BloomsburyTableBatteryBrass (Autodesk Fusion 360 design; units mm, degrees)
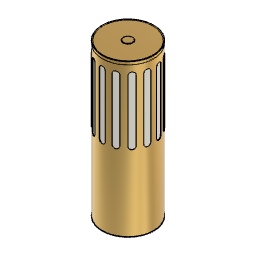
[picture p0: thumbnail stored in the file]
sketch "Sketch2" plane through (0, 0, 0) normal (0, 0, 1) x axis (1, 0, 0)
  circle C1 centre (0, 0) radius 27
  point P1 (0, 0)
  point P2 (0, 0)
  coincident P1 P2
  dimension "d1" diameter C1 = 54
extrude "Extrude1" new body sketch "Sketch2" along normal blind 158
shell "Shell1" innerThickness 1
sketch "Sketch3" plane through (0, 0, 158) normal (0, 0, 1) x axis (-1, 0, 0)
  circle C1 centre (0, 0) radius 26
  circle C2 centre (0, 0) radius 27
  circle C3 centre (0, 0) radius 27
  point P1 (0, 0)
  point P3 (0, 0)
  coincident P1 P3
  dimension "d69" diameter C3 = 54
extrude "Extrude2" new body sketch "Sketch3" along normal blind 0.5
sketch "Sketch4" plane through (0, 0, 0) normal (0, 0, -1) x axis (1, 0, 0)
  circle C1 centre (0, 0) radius 26
  circle C2 centre (0, 0) radius 27
  circle C3 centre (0, 0) radius 27
  point P1 (0, 0)
  point P3 (0, 0)
  coincident P1 P3
  dimension "d70" diameter C3 = 54
extrude "Extrude3" new body sketch "Sketch4" along normal blind 0.5
work_plane "WorkPlane1" AlongDistance -50
sketch "Sketch5" plane through (0, -50, 0) normal (0, 1, 0) x axis (1, 0, 0)
  line L1 (27, -158.5) -> (-27, -158.5)
  line L2 (0, -2.5) -> (0, -20)
  line L3 (-3, -81.5) -> (-3, -145.5)
  line L4 (0, -125) -> (0, -85)
  line L5 (3, -81.5) -> (3, -145.5)
  arc A1 centre (0, -145.5) radius 3 clockwise from (0, -148.5) to (-3, -145.5)
  arc A2 centre (0, -81.5) radius 3 clockwise from (-3, -81.5) to (0, -78.5)
  arc A3 centre (0, -145.5) radius 3 clockwise from (3, -145.5) to (0, -148.5)
  arc A4 centre (0, -81.5) radius 3 clockwise from (0, -78.5) to (3, -81.5)
  point P9 (0, -145.5)
  point P8 (0, -148.5)
  point P13 (0, -81.5)
  point P12 (0, -78.5)
  point P6 (-3, -145.5)
  point P15 (3, -145.5)
  point P7 (-3, -81.5)
  point P17 (3, -81.5)
  point P16 (0, -148.5)
  point P19 (0, -78.5)
  vertical L3
  tangent L3 A1
  vertical L4
  coincident P9 L4
  coincident P8 L4
  tangent L3 A2
  coincident L4 P13
  coincident L4 P12
  symmetric P6 L4 P15
  symmetric P7 L4 P17
  symmetric P8 L4 P16
  symmetric A1 L4 A3
  symmetric L4 P12 P19
  symmetric L4 A2 A4
  dimension "d75" distance L3 L4 = 3
  dimension "d77" distance P8 P19 = 70
  dimension "d78" distance L1 P8 = 10
emboss "Emboss1" sketch "Sketch5" Depth -8 Horizontal Distance 0 Vertical Distance 0 Rotation Angle 0
fillet "Fillet7" radius 0.1
circular_pattern "C-Pattern1" countU 14 TotalAngle 360
fillet "Fillet2" radius 0.1
sketch "Sketch6" plane through (0, 0, 0) normal (0, 0, 1) x axis (-1, 0, 0)
  circle C1 centre (0, 0) radius 26.9
  circle C2 centre (0, 0) radius 26.75
  point P1 (0, 0)
  point P3 (0, 0)
  coincident P1 P3
  dimension "d25" diameter C2 = 53.5
extrude "Extrude4" new body sketch "Sketch6" profile of C2 along normal blind 155
work_plane "WorkPlane2" RotateAngle 0
sketch "Sketch7" plane through (0, 27, 16.5829) normal (0, 1, 0) x axis (1, 0, 0)
  line L1 (-27, 16.9829) -> (27, 16.9829)
  circle C1 centre (0, 9.4829) radius 5.5
  circle C2 centre (0, 9.4829) radius 3.5
  point P1 (0, 0)
  point P2 (0, 9.4829)
  vertical P1 P2
  concentric C1 C2
  dimension "d29" diameter C1 = 11
  dimension "d30" distance P2 L1 = 7.5
  dimension "d31" diameter C2 = 7
sketch "Sketch8" plane through (0, 27, 16.5829) normal (0, 1, 0) x axis (1, 0, 0)
  circle C1 centre (0, 16) radius 3
  dimension "d38" diameter C1 = 6
sketch "Sketch9" plane through (0, 0, -0.5) normal (0, 0, -1) x axis (1, 0, 0)
  circle C1 centre (0, 0) radius 26.9
  circle C2 centre (0, 0) radius 6
  point P1 (0, 0)
  point P3 (0, 0)
  coincident P1 P3
  dimension "d43" diameter C2 = 12
extrude "Extrude8" cut sketch "Sketch9" profile of C2 against normal blind 0.5 taper -40
sketch "Sketch10" plane through (0, 0, 0) normal (0, 0, -1) x axis (1, 0, 0)
  circle C1 centre (0, 0) radius 26.75
  circle C2 centre (0, 0) radius 5.58
  point P1 (0, 0)
  point P3 (0, 0)
  coincident P1 P3
extrude "Extrude9" new body sketch "Sketch10" profile of C2 to an object
sketch "Sketch11" plane through (0, 0, -0.5) normal (0, 0, -1) x axis (1, 0, 0)
  line L1 (-2.3094, 0) -> (-1.1547, 2)
  line L2 (-1.1547, -2) -> (-2.3094, 0)
  line L3 (1.1547, -2) -> (-1.1547, -2)
  line L4 (2.3094, 0) -> (1.1547, -2)
  line L5 (1.1547, 2) -> (2.3094, 0)
  line L6 (-1.1547, 2) -> (1.1547, 2)
  circle C1 centre (0, 0) radius 5.58
  point P1 (0, 0)
  point P9 (0, 0)
  coincident P1 P9
  dimension "d51" distance P9 L6 = 2
extrude "Extrude10" cut sketch "Sketch11" profile of L1 L2 L3 L4 L5 L6 against normal blind 0.49
fillet "Fillet4" radius 0.1
sketch "Sketch12" plane through (0, 0, 158.5) normal (0, 0, 1) x axis (-1, 0, 0)
  circle C1 centre (0, 0) radius 26.9
  circle C2 centre (0, 0) radius 5
  point P1 (0, 0)
  point P3 (0, 0)
  coincident P1 P3
  dimension "d56" diameter C2 = 10
extrude "Extrude14" cut sketch "Sketch12" profile of C2 against normal blind 0.5
sketch "Sketch14" plane through (0, 0, 155) normal (0, 0, 1) x axis (-1, 0, 0)
  circle C1 centre (0, 0) radius 26.75
  circle C2 centre (0, 0) radius 4.75
  point P1 (0, 0)
  point P3 (0, 0)
  coincident P1 P3
  dimension "d83" diameter C2 = 9.5
extrude "Extrude15" new body sketch "Sketch14" profile of C2 along normal blind 3.7
fillet "Fillet8" radius 0.2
